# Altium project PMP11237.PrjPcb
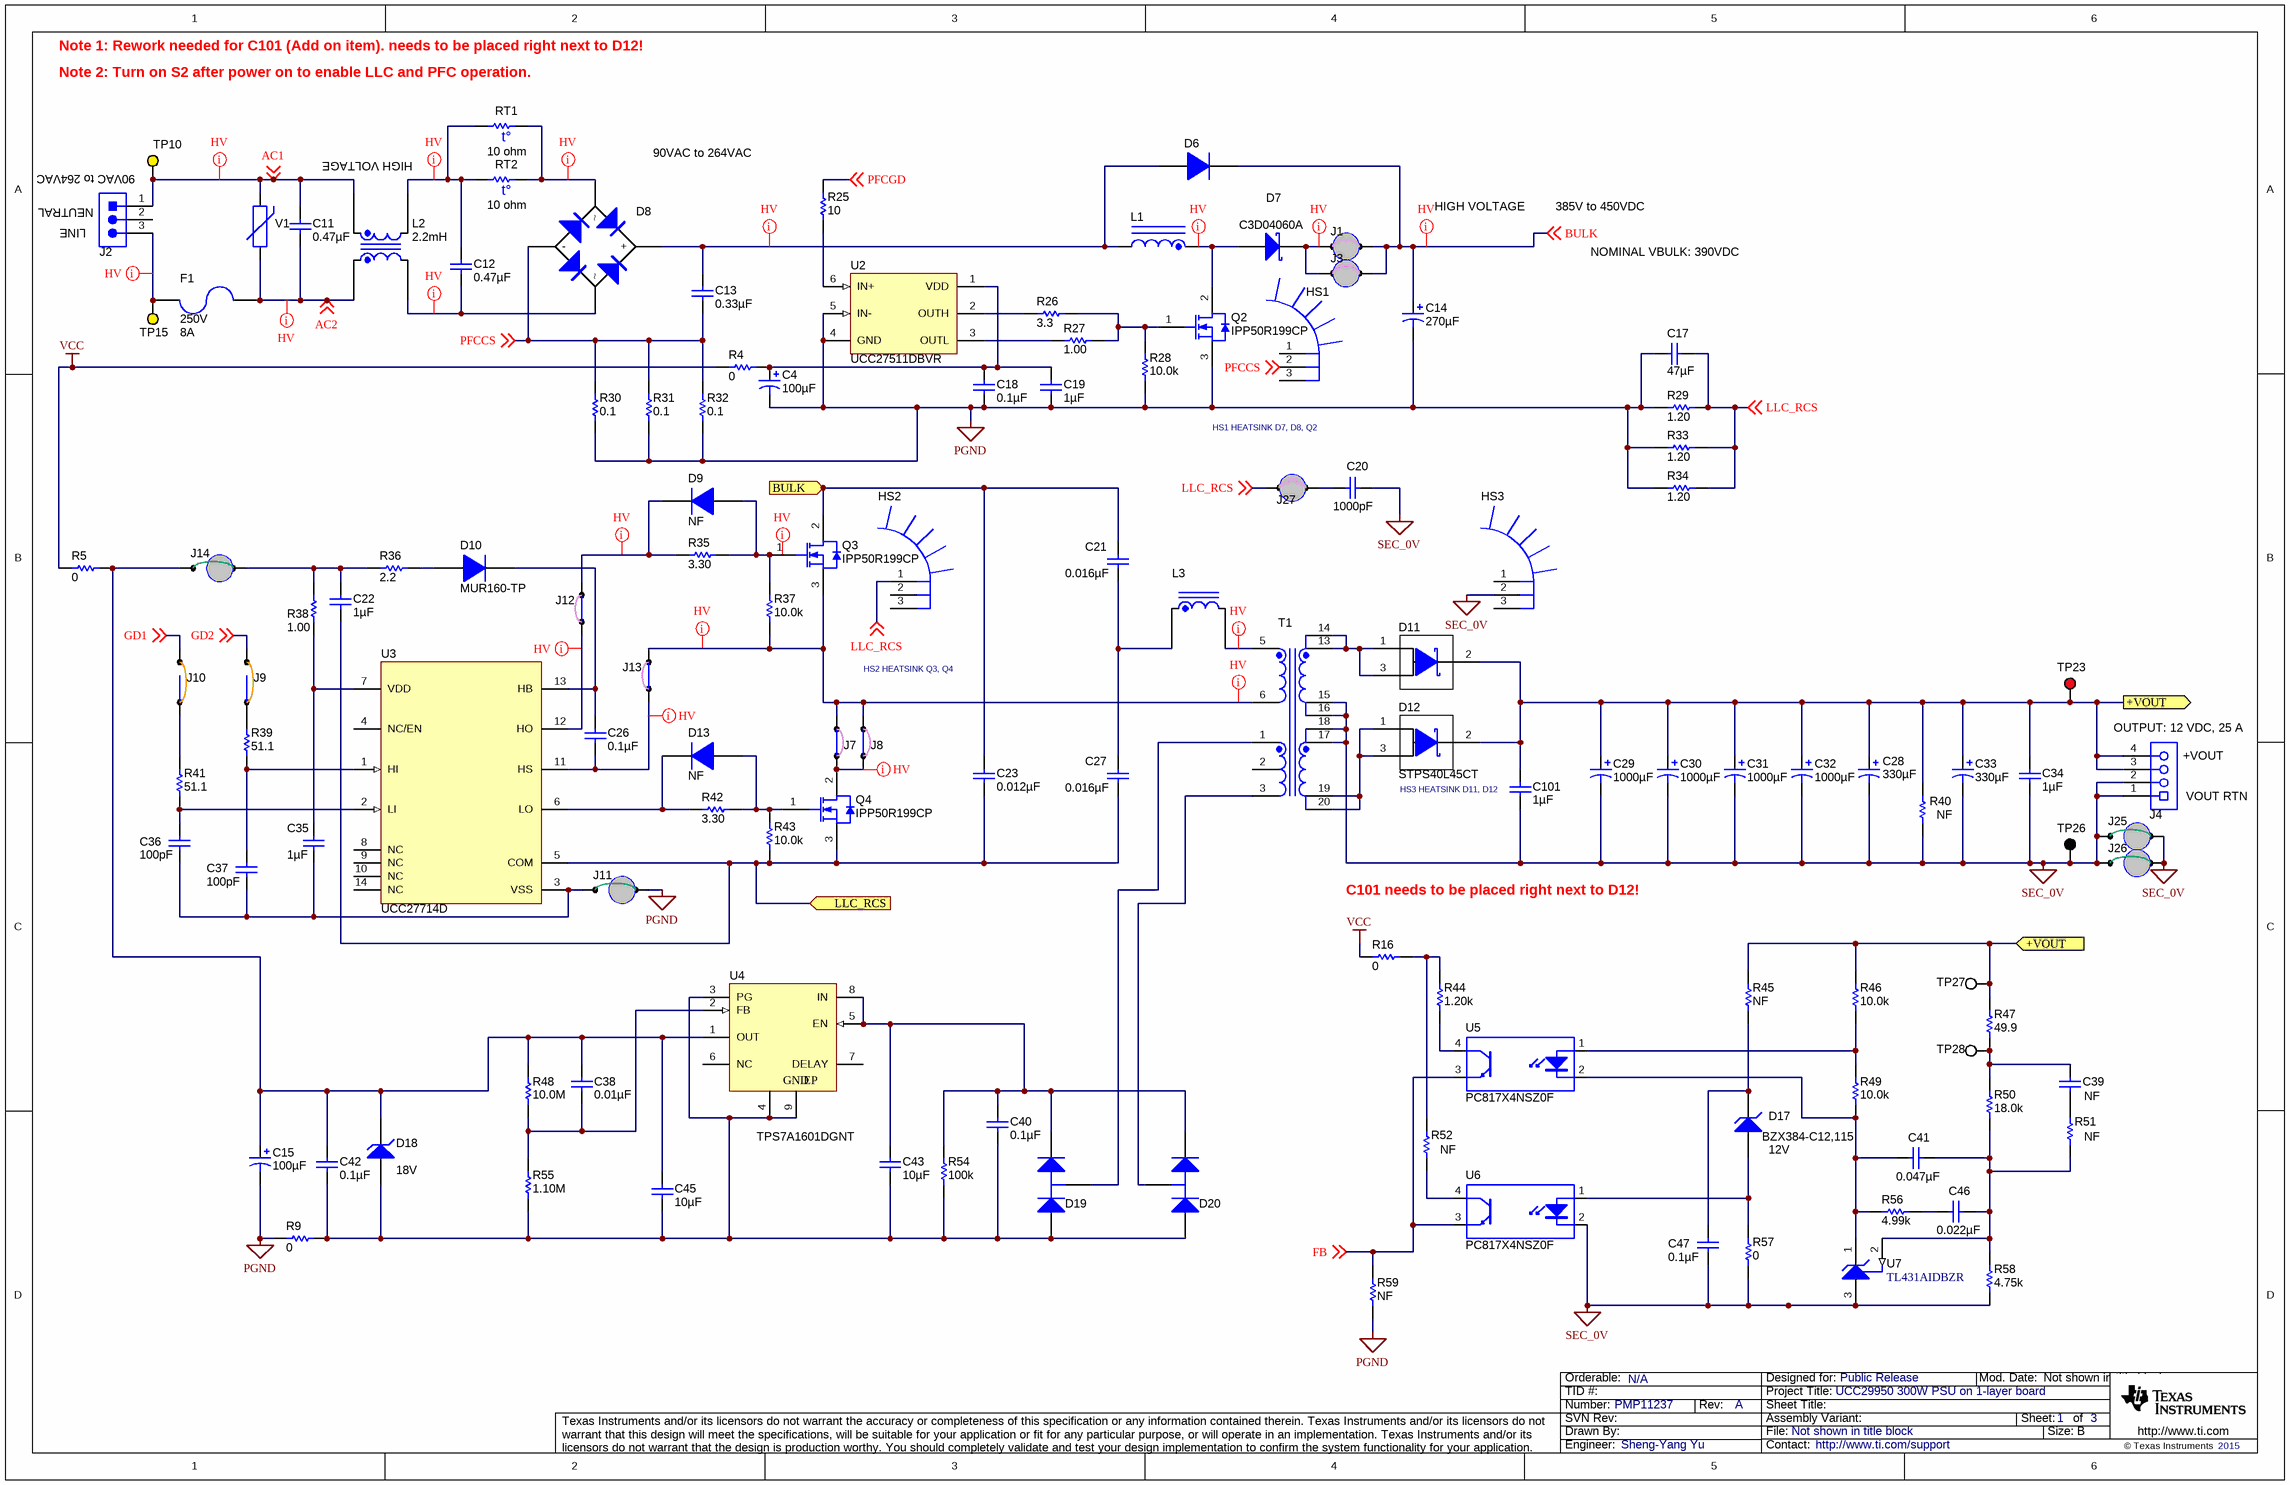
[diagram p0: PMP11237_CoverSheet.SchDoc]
CopyrightYear: 2015; EVM_Orderable: N/A; PCB_Layout: Sheng-Yang Yu; PCB_Rev: A; PRJ_Customer: Public Release; PRJ_Engineer: Sheng-Yang Yu; PRJ_Number: PMP11237; PRJ_Title: UCC29950 300W PSU on 1-layer board; SCH_Rev: A; TechSupport: http://www.ti.com/support
3 sheets, 215 parts. Net scope: flat (ports and power ports of the same name join across sheets).
Board file: PMP11237_TID.PcbDoc
Sheets:
  PMP11237_CoverSheet.SchDoc
  PMP11237_BlankSheet.SchDoc
  PMP11237_TID_Hardware.SchDoc

## Sheet PMP11237_CoverSheet.SchDoc
size 431 x 279 mm; Date: Not shown in title block; ApprovedBy: Not shown in title block; CheckedBy: Not shown in title block; Author: Not shown in title block; CompanyName: Not shown in title block; Engineer: Not shown in title block; Organization: Not shown in title block; Address1: Not shown in title block; Address2: Not shown in title block; Address3: Not shown in title block; Address4: Not shown in title block; DocumentNumber: 1; Revision: Use project parameter SCH_Rev; SheetNumber: 1; SheetTotal: 3; PageSetup: Record=PageOptions¦CenterHorizontal=True¦CenterVertical=True¦PrintScale=1.00¦XCorrection=1.00¦YCorrection=1.00¦PrintKind=0¦BorderSize=5000000¦LeftOffset=0¦BottomOffset=0¦Orientation=2¦PaperLength=1000¦PaperWidth=1000¦Scale=100¦PaperSource=15¦PrintQuality=600¦MediaType=1¦DitherType=10¦PaperKind=Letter¦PrintScaleMode=1

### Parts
C4  ValueDisplayed: 100µF  [CAPPR250W50D630H1120]  (hidden comment: EEU-EB1E101S)
C11  ValueDisplayed: 0.47µF  [CAPRR2250W80L2550T850H1750]  (hidden comment: ECQ-U2A474ML)
C12  ValueDisplayed: 0.47µF  [CAPRR2250W80L2550T850H1750]  (hidden comment: ECQ-U2A474ML)
C13  ValueDisplayed: 0.33µF  [CAPRR1500W80L1750T950H1750]  (hidden comment: ECQ-U2A334ML)
C14  ValueDisplayed: 270µF  [380LQ_3000x3000]  (hidden comment: 380LQ271M450K022)
C15  ValueDisplayed: 100µF  [CAPPR250W50D630H1120]  (hidden comment: EEU-EB1E101S)
C17  ValueDisplayed: 47µF  [1210]  (hidden comment: GRM32ER70J476KE20L)
C18  ValueDisplayed: 0.1µF  [0805_HV]  (hidden comment: 08055C104JAT2A)
C19  ValueDisplayed: 1µF  [0805_HV]  (hidden comment: GRM21BR71H105KA12L)
C20  ValueDisplayed: 1000pF  [DE_800x1200x800]  (hidden comment: DE1E3KX102MA5BA01)
C21  value 0.016µF  [ECWH_8123HA]  (hidden comment: ECW-F6163JL)
C22  ValueDisplayed: 1µF  [0603]  (hidden comment: UMK107AB7105KA-T)
C23  ValueDisplayed: 0.012µF  [ECWH_8123HA]  (hidden comment: ECW-H8123HA)
C26  ValueDisplayed: 0.1µF  [1206]  (hidden comment: C3216C0G1E104J)
C27  value 0.016µF  [ECWH_8123HA]  (hidden comment: ECW-F6163JL)
C28  ValueDisplayed: 330µF  [PS_1000x1250]  (hidden comment: APS-160ELL331MJC5S)
C29  ValueDisplayed: 1000µF  [FR_800x2000]  (hidden comment: EEU-FR1C102L)
C30  ValueDisplayed: 1000µF  [FR_800x2000]  (hidden comment: EEU-FR1C102L)
C31  ValueDisplayed: 1000µF  [FR_800x2000]  (hidden comment: EEU-FR1C102L)
C32  ValueDisplayed: 1000µF  [FR_800x2000]  (hidden comment: EEU-FR1C102L)
C33  ValueDisplayed: 330µF  [PS_1000x1250]  (hidden comment: APS-160ELL331MJC5S)
C34  ValueDisplayed: 1µF  [0805_HV]  (hidden comment: GRM21BR71H105KA12L)
C35  ValueDisplayed: 1µF  [1206]  (hidden comment: 12063C105KAT2A)
C36  ValueDisplayed: 100pF  [0603]  (hidden comment: 06035A101FAT2A)
C37  ValueDisplayed: 100pF  [0603]  (hidden comment: 06035A101FAT2A)
C38  ValueDisplayed: 0.01µF  [0603]  (hidden comment: C0603C103K5RACTU)
C39  NF  [0603]
C40  ValueDisplayed: 0.1µF  [0805_HV]  (hidden comment: 08055C104JAT2A)
C41  ValueDisplayed: 0.047µF  [0805_HV]  (hidden comment: 08055C473KAT2A)
C42  ValueDisplayed: 0.1µF  [0805_HV]  (hidden comment: 08055C104JAT2A)
C43  ValueDisplayed: 10µF  [1206_190]  (hidden comment: CGA5L3X5R1H106K160AB)
C45  ValueDisplayed: 10µF  [1206_190]  (hidden comment: CGA5L3X5R1H106K160AB)
C46  ValueDisplayed: 0.022µF  [0603]  (hidden comment: 885012206091)
C47  ValueDisplayed: 0.1µF  [0603]  (hidden comment: C0603C104K4RACTU)
C101  ValueDisplayed: 1µF  [1206]  (hidden comment: CC1206KKX7R7BB105)
D6  1N5406  [DO-201AD]  (value not drawn)
D7  C3D04060A  [TO-220-F2]
D8  GBU8J-BP  [GBU]  (value not drawn)
D9  NF  [sod-323]
D10  MUR160-TP  [DO-41]
D11  STPS40L45CT  [TO-220AB]  (value not drawn)
D12  STPS40L45CT  [TO-220AB]
D13  NF  [sod-323]
D17  BZX384-C12,115  value 12V  [sod-323]
D18  value 18V  [SOD-123]  (hidden comment: MMSZ5248B-7-F)
D19  BAV99,215  [SOT-23]  (value not drawn)
D20  BAV99,215  [SOT-23]  (value not drawn)
F1  VAC_V: 250V  Irating_A: 8A  [FUSE_0216]  (hidden comment: 0216008.MXESPP)
HS1  782653B04250G  [HEATSINK_782653B04250G]  (value not drawn)
HS2  782653B04250G  [HEATSINK_782653B04250G]  (value not drawn)
HS3  782653B04250G  [HEATSINK_782653B04250G]  (value not drawn)
J1  923345-07-C  [CONN_923345-07-C]  (value not drawn)
J2  1-1318301-3  [TE_1-1318301-3]  (value not drawn)
J3  923345-07-C  [CONN_923345-07-C]  (value not drawn)
J4  ED120/4DS  [CONN_ED120_4DS]  (value not drawn)
J7  923345-07-C  [CONN_923345-07-C]  (value not drawn)
J8  923345-07-C  [CONN_923345-07-C]  (value not drawn)
J9  923345-03-C  [923345-03-C]  (value not drawn)
J10  923345-03-C  [923345-03-C]  (value not drawn)
J11  923345-05-C  [923345-05-C]  (value not drawn)
J12  923345-07-C  [CONN_923345-07-C]  (value not drawn)
J13  923345-07-C  [CONN_923345-07-C]  (value not drawn)
J14  923345-05-C  [923345-05-C]  (value not drawn)
J25  923345-05-C  [923345-05-C]  (value not drawn)
J26  923345-05-C  [923345-05-C]  (value not drawn)
J27  923345-07-C  [CONN_923345-07-C]  (value not drawn)
L1  RLTI-1108  [RLTI-1108]  (value not drawn)
L2  ValueDisplayed: 2.2mH  [WE-CMB_XL]  (hidden comment: 7448258022)
L3  75PR8106  [Vitec_75P8106]  (value not drawn)
Q2  IPP50R199CP  [TO-262_100mil]
Q3  IPP50R199CP  [TO-262_100mil]
Q4  IPP50R199CP  [TO-262_100mil]
R4  ValueDisplayed: 0  [1206]  (hidden comment: CRCW12060000Z0EA)
R5  ValueDisplayed: 0  [1206]  (hidden comment: CRCW12060000Z0EA)
R9  ValueDisplayed: 0  [1206]  (hidden comment: CRCW12060000Z0EA)
R16  ValueDisplayed: 0  [1206]  (hidden comment: CRCW12060000Z0EA)
R25  ValueDisplayed: 10  [0603]  (hidden comment: CRCW060310R0JNEA)
R26  ValueDisplayed: 3.3  [0603]  (hidden comment: CRCW06033R30JNEA)
R27  ValueDisplayed: 1.00  [0603]  (hidden comment: CRCW06031R00FKEA)
R28  value 10.0k  [0603]  (hidden comment: CRCW060310K0FKEA)
R29  ValueDisplayed: 1.20  [2512M]  (hidden comment: ERJ-1TRQF1R2U)
R30  ValueDisplayed: 0.1  [2512]  (hidden comment: CSRN2512FTR100)
R31  ValueDisplayed: 0.1  [2512]  (hidden comment: CSRN2512FTR100)
R32  ValueDisplayed: 0.1  [2512]  (hidden comment: CSRN2512FTR100)
R33  ValueDisplayed: 1.20  [2512M]  (hidden comment: ERJ-1TRQF1R2U)
R34  ValueDisplayed: 1.20  [2512M]  (hidden comment: ERJ-1TRQF1R2U)
R35  value 3.30  [1206]  (hidden comment: ERJ-8RQF3R3V)
R36  ValueDisplayed: 2.2  [0805_HV]  (hidden comment: CRCW08052R20JNEA)
R37  value 10.0k  [0603]  (hidden comment: CRCW060310K0FKEA)
R38  value 1.00  [0805_HV]  (hidden comment: ERJ-6RQF1R0V)
R39  ValueDisplayed: 51.1  [0603]  (hidden comment: CRCW060351R1FKEA)
R40  NF  [1206]
R41  ValueDisplayed: 51.1  [0603]  (hidden comment: CRCW060351R1FKEA)
R42  value 3.30  [1206]  (hidden comment: ERJ-8RQF3R3V)
R43  value 10.0k  [0603]  (hidden comment: CRCW060310K0FKEA)
R44  ValueDisplayed: 1.20k  [1206]  (hidden comment: RC1206FR-071K2L)
R45  ValueDisplayed: NF  [1206]  (hidden comment: CRCW1206100RFKEA)
R46  ValueDisplayed: 10.0k  [0805_HV]  (hidden comment: CRCW080510K0FKEA)
R47  value 49.9  [1206]  (hidden comment: ERJ-8ENF49R9V)
R48  ValueDisplayed: 10.0M  [0603]  (hidden comment: RC0603FR-0710ML)
R49  value 10.0k  [0603]  (hidden comment: CRCW060310K0FKEA)
R50  value 18.0k  [0603]  (hidden comment: RC0603FR-0718KL)
R51  NF  [0603]
R52  NF  [0603]
R54  ValueDisplayed: 100k  [0603]  (hidden comment: CRCW0603100KFKEA)
R55  ValueDisplayed: 1.10M  [0603]  (hidden comment: CRCW06031M10FKEA)
R56  ValueDisplayed: 4.99k  [0603]  (hidden comment: CPF0603B4K99E)
R57  value 0  [0603]  (hidden comment: CRCW06030000Z0EA)
R58  ValueDisplayed: 4.75k  [0603]  (hidden comment: CRCW06034K75FKEA)
R59  ValueDisplayed: NF  [1206]  (hidden comment: CRCW12061K00FKEA)
RT1  value 10 ohm  [Thermistor_CL-40]  (hidden comment: CL-60)
RT2  value 10 ohm  [Thermistor_CL-40]  (hidden comment: CL-60)
T1  RLTI-1115  [Renco_RLTI-1115]  (value not drawn)
TP10  5014  [Keystone5014]  (value not drawn)
TP15  5014  [Keystone5014]  (value not drawn)
TP23  5010  [Keystone5010]  (value not drawn)
TP26  5011  [Keystone5011]  (value not drawn)
TP27  5012  [Keystone5012]  (value not drawn)
TP28  5012  [Keystone5012]  (value not drawn)
U2  UCC27511DBVR  [DBV0006A_N]
U3  UCC27714D  [D0014A_N]
U4  TPS7A1601DGNT  [DGN0008C_N]
U5  PC817X4NSZ0F  [DIP762W60P254L460H350Q4B]
U6  PC817X4NSZ0F  [DIP762W60P254L460H350Q4B]
U7  TL431AIDBZR  [DBZ0003A_N]
V1  B72207S2301K101  [VAR_S07K300E2]  (value not drawn)

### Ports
+VOUT, BULK, LLC_RCS

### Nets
PGND: C4.2(-) C14.2(-) C15.2(-) C17.2 C18.2 C19.2 J11.2 Q2.3(S) R9.2 R28.2 R29.2 R30.1 R31.1 R32.1 R33.2 R34.2 R59.1 U2.4(GND) U2.5(IN-)
SEC_0V: C20.1 C28.2(-) C29.2(-) C30.2(-) C31.2(-) C32.2(-) C33.2(-) C34.2 C47.2 C101.2 HS3.2 J4.1 J4.2 J25.1 J25.2 J26.1 J26.2 R40.1 R57.1 R58.1 T1.15 T1.16 T1.17 T1.18 TP26.1 U6.2(K) U7.3(ANODE)
VCC: R4.1 R5.2 R16.1
+VOUT: C28.1(+) C29.1(+) C30.1(+) C31.1(+) C32.1(+) C33.1(+) C34.1 C101.1 D11.2(K) D12.2(K) J4.3 J4.4 R40.2 R45.2 R46.2 R47.2 TP23.1 TP27.1 ; port +VOUT
AC1: C11.1 J2.1 L2.1 TP10.1 V1.2 ; off-sheet AC1
AC2: C11.2 F1.1 L2.6 V1.1 ; off-sheet AC2
BULK: C14.1(+) D6.1(K) J1.2 J3.2 ; off-sheet BULK
BULK: C21.1 C23.1 Q3.2(D) ; port BULK  [a separate net that carries the same name]
FB: R59.2 U5.3(E) U6.3(E) ; off-sheet FB
GD1: J10.1 ; off-sheet GD1
GD2: J9.1 ; off-sheet GD2
LLC_RCS: C22.1 C23.2 C27.2 Q4.3(S) R43.2 U3.5(COM) ; port LLC_RCS
LLC_RCS: C17.1 HS2.1 J27.2 R29.1 R33.1 R34.1 ; off-sheet LLC_RCS  [a separate net that carries the same name]
PFCCS: C13.2 D8.4(-) HS1.2 R30.2 R31.2 R32.2 ; off-sheet PFCCS
PFCGD: R25.2 ; off-sheet PFCGD
NetC4_1: C4.1(+) C18.1 C19.1 R4.2 U2.1(VDD)
NetC12_1: C12.1 L2.12 RT1.1 RT2.1
NetC12_2: C12.2 D8.3 L2.7
NetC13_1: C13.1 D6.2(A) D8.1(+) L1.9
NetC15_1: C15.1(+) C38.1 C42.1 C45.1 D18.1(K) J14.1 R5.1 R48.2 U4.1(OUT)
NetC20_2: C20.2 J27.1
NetC21_2: C21.2 C27.1 L3.1
NetC22_2: C22.2 J14.2 R36.1 R38.2
NetC26_1: C26.1 D10.1(K) U3.13(HB)
NetC26_2: C26.2 J13.2 U3.11(HS)
NetC35_1: C35.1 R38.1 U3.7(VDD)
NetC35_2: C35.2 C36.2 C37.1 J11.1 U3.3(VSS)
NetC36_1: C36.1 R41.1 U3.2(LI)
NetC37_2: C37.2 R39.1 U3.1(HI)
NetC38_2: C38.2 R48.1 R55.1 U4.2(FB)
NetC39_1: C39.1 R47.1 R50.2 TP28.1
NetC39_2: C39.2 R51.1
NetC40_1: C40.1 C43.1 D19.2(K) D20.2(K) R54.2 U4.5(EN) U4.8(IN)
NetC40_2: C40.2 C42.2 C43.2 C45.2 D18.2(A) D19.1(A) D20.1(A) R9.1 R54.1 R55.2 U4.3(PG) U4.4(GND) U4.9(EP)
NetC41_1: C41.1 C46.1 R50.1 R51.2 R58.2 U7.2(REF)
NetC41_2: C41.2 R49.1 R56.1 U5.2(K) U7.1(CATHODE)
NetC46_2: C46.2 R56.2
NetC47_1: C47.1 D17.1(K) R45.1
NetD7_1: D7.1(K) J1.1 J3.1
NetD7_2: D7.2(A) L1.5 Q2.2(D)
NetD8_2: D8.2 RT1.2 RT2.2
NetD9_1: D9.1(K) J12.1 R35.1
NetD9_2: D9.2(A) Q3.1(G) R35.2 R37.2
NetD10_2: D10.2(A) R36.2
NetD11_1: D11.1(A) D11.3(A) T1.13 T1.14
NetD12_1: D12.1(A) D12.3(A) T1.19 T1.20
NetD13_1: D13.1(K) R42.1 U3.6(LO)
NetD13_2: D13.2(A) Q4.1(G) R42.2 R43.1
NetD17_2: D17.2(A) R57.2 U6.1(A)
NetD19_3: D19.3(C) T1.1
NetD20_3: D20.3(C) T1.3
NetF1_2: F1.2 J2.3 TP15.1
NetJ7_1: J7.1 J8.1 J13.1 Q3.3(S) R37.1 T1.6
NetJ7_2: J7.2 J8.2 Q4.2(D)
NetJ9_2: J9.2 R39.2
NetJ10_2: J10.2 R41.2
NetJ12_2: J12.2 U3.12(HO)
NetL3_6: L3.6 T1.5
NetQ2_1: Q2.1(G) R26.2 R27.2 R28.1
NetR16_2: R16.2 R44.2 R52.1
NetR25_1: R25.1 U2.6(IN+)
NetR26_1: R26.1 U2.2(OUTH)
NetR27_1: R27.1 U2.3(OUTL)
NetR44_1: R44.1 U5.4(C)
NetR46_1: R46.1 R49.2 U5.1(A)
NetR52_2: R52.2 U6.4(C)

Not connected (* = marked no-connect by the designer): HS1 1 3; HS2 2 3; HS3 1 3; J2 2; T1 2; U3 4(NC/EN) 8(NC) 9(NC) 10(NC) 14(NC); U4 6(NC) 7(DELAY)

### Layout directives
net class HV: (no net found under the mark), AC1, AC2, BULK, NetC12_1, NetC12_2, NetC13_1, NetC26_2, NetD7_1, NetD7_2, NetD8_2, NetD9_1, NetF1_2, NetJ7_1, NetJ7_2, NetJ12_2, NetL3_6

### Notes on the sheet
- Note 1: Rework needed for C101 (Add on item). needs to be placed right next to D12!
- (near RT1) Note 2: Turn on S2 after power on to enable LLC and PFC operation.
- HIGH VOLTAGE
- (near D8) 90VAC to 264VAC
- (near J2) NEUTRAL
- (near J2) LINE
- 90VAC to 264VAC
- 385V to 450VDC
- NOMINAL VBULK: 390VDC
- HS1 HEATSINK D7, D8, Q2
- HS2 HEATSINK Q3, Q4
- (near J4) OUTPUT: 12 VDC, 25 A
- (near J4) +VOUT
- HS3 HEATSINK D11, D12
- VOUT RTN
- C101 needs to be placed right next to D12!

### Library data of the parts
C4 C15 = EEU-EB1E101S: CAP, AL, 100 µF, 25 V, +/- 20%, TH; Manufacturer: Panasonic; Polarized: Y; CompType: Capacitor; Value: 100uF; U/M: EA; Cap_F: 0.0001; Tolerance_%: 20; Value1: Unknown; VDC_V: 25; Value2: 25V; IRMS_A: 0.095; TaMin_C: -40; TaMax_C: 105; Cap_Case: Radial 6.3x11.2
C11 C12 = ECQ-U2A474ML: CAP, Film, 0.47uF, 275V, +/-20%, TH; Manufacturer: Panasonic; Polarized: N; CompType: Capacitor; U/M: EA; Cap_F: 0.00000047; Tolerance_%: 20; Value1: Unknown; VDC_V: 275; TaMin_C: -40; TaMax_C: 100; Cap_Case: Radial 25x8.5x18.5
C13 = ECQ-U2A334ML: CAP, Film, 0.33uF, 275V, +/-20%, TH; Manufacturer: Panasonic; Polarized: N; CompType: Capacitor; U/M: EA; Cap_F: 0.00000033; Tolerance_%: 20; Value1: Unknown; VDC_V: 275; TaMin_C: -40; TaMax_C: 100; Cap_Case: Radial,17.5x17.5x9.5mm
C14 = 380LQ271M450K022: CAP, AL, 270 µF, 450 V, +/- 20%, 0.737 ohm, TH; Manufacturer: Cornell Dubilier Electronics; Polarized: Y; CompType: Capacitor; Value: 270uF; U/M: EA; Cap_F: 0.00027; Tolerance_%: 20; VDC_V: 450; Value2: 450V; ESR_ohm: 0.737; IRMS_A: 1.78; TaMin_C: -25; TaMax_C: 85; Cap_Case: 30x30mm
C17 = GRM32ER70J476KE20L: CAP, CERM, 47uF, 6.3V, +/-10%, X7R, 1210; Manufacturer: MuRata; Polarized: N; CompType: Capacitor; U/M: EA; Cap_F: 0.000047; Tolerance_%: 10; Value1: Unknown; VDC_V: 6.3; TaMin_C: -55; TaMax_C: 125
C18 C40 C42 = 08055C104JAT2A: CAP, CERM, 0.1uF, 50V, +/-5%, X7R, 0805; Manufacturer: AVX; Polarized: N; CompType: Capacitor; U/M: EA; Cap_F: 0.0000001; Tolerance_%: 5; ESR_Ohm: 0.024; Value1: 0.024 ohm; VDC_V: 50; TaMin_C: -55; TaMax_C: 125; Cap_Case: 0805
C19 C34 = GRM21BR71H105KA12L: CAP, CERM, 1uF, 50V, +/-10%, X7R, 0805; Manufacturer: MuRata; Polarized: N; CompType: Capacitor; U/M: EA; Cap_F: 0.000001; Tolerance_%: 10; Value1: Unknown; VDC_V: 50; TaMin_C: -55; TaMax_C: 125; Cap_Case: 0805
C20 = DE1E3KX102MA5BA01: CAP, CERM, 1000pF, 250V, +/-20%, E, Disc, 8x12mm; Manufacturer: MuRata; Polarized: N; CompType: Capacitor; U/M: EA; Cap_F: 0.000000001; Tolerance_%: 20; Value1: Unknown; VDC_V: 250; TaMin_C: -25; TaMax_C: 85
C21 C27 = ECW-H8123HA: CAP FILM 0.016UF 630VDC RADIAL; Manufacturer: Panasonic Electronic Components; Dielectric Material: Polypropylene (PP), Metallized; Voltage Rating - DC: 630V; Tolerance_%: ±5%
C22 = UMK107AB7105KA-T: CAP, CERM, 1 µF, 50 V, +/- 10%, X7R, 0603; Manufacturer: Taiyo Yuden; Polarized: N; CompType: Capacitor; Value: 1uF; U/M: EA; Cap_F: 0.000001; Tolerance_%: 10; Value1: Unknown; VDC_V: 50; Value2: 50V; TaMin_C: -55; TaMax_C: 125
C23 = ECW-H8123HA: CAP, Film, 0.012uF, 800V, +/-3%, TH; Manufacturer: Panasonic; Polarized: N; CompType: Capacitor; U/M: EA; Cap_F: 0.000000012; Tolerance_%: 3; Value1: Unknown; VDC_V: 800; TaMin_C: -40; TaMax_C: 105
C26 = C3216C0G1E104J: CAP, CERM, 0.1 µF, 25 V, +/- 5%, C0G/NP0, 1206; Manufacturer: TDK; Polarized: N; CompType: Capacitor; Value: 0.1uF; U/M: EA; Cap_F: 0.0000001; Tolerance_%: 5; Value1: Unknown; VDC_V: 25; Value2: 25V; TaMin_C: -55; TaMax_C: 125
C28 C33 = APS-160ELL331MJC5S: CAP, AL, 330uF, 16V, +/-20%, 0.014 ohm, TH; Manufacturer: Nippon Chemi-Con; Polarized: Y; CompType: Capacitor; U/M: EA; Cap_F: 0.00033; Tolerance_%: 20; VDC_V: 16; ESR_Ohm: 0.014; IRMS_A: 5.05; TaMin_C: -55; TaMax_C: 105
C29-C32 = EEU-FR1C102L: CAP, AL, 1000uF, 16V, +/-20%, 0.03 ohm, TH; Manufacturer: Panasonic; Polarized: Y; CompType: Capacitor; U/M: EA; Cap_F: 0.001; Tolerance_%: 20; VDC_V: 16; ESR_Ohm: 0.03; IRMS_A: 1.56; TaMin_C: -40; TaMax_C: 105; Cap_Case: 8x20
C35 = 12063C105KAT2A: CAP, CERM, 1 µF, 25 V, +/- 10%, X7R, 1206; Manufacturer: AVX; Polarized: N; CompType: Capacitor; Value: 1uF; U/M: EA; Cap_F: 0.000001; Tolerance_%: 10; ESR_ohm: 0.013; Value1: 0.013 ohm; VDC_V: 25; Value2: 25V; TaMin_C: -55; TaMax_C: 125
C36 C37 = 06035A101FAT2A: CAP, CERM, 100pF, 50V, +/-1%, C0G/NP0, 0603; Manufacturer: AVX; CompType: Capacitor; Tolerance_%: 1; Value1: Unknown; VDC_V: 50; U/M: EA; Polarized: N; Cap_F: 0.0000000001; TaMin_C: -55; TaMax_C: 125
C38 = C0603C103K5RACTU: CAP, CERM, 0.01 µF, 50 V, +/- 10%, X7R, 0603; Manufacturer: Kemet; Polarized: N; CompType: Capacitor; Value: 0.01uF; U/M: EA; Cap_F: 0.00000001; Tolerance_%: 10; Value1: Unknown; VDC_V: 50; Value2: 50V; TaMin_C: -55; TaMax_C: 125
C39 = GRM1885C1E102JA01D: CAP, CERM, 1000pF, 25V, +/-5%, C0G/NP0, 0603; Manufacturer: MuRata; Polarized: N; CompType: Capacitor; U/M: EA; Cap_F: 0.000000001; Tolerance_%: 5; Value1: Unknown; VDC_V: 25; TaMin_C: -55; TaMax_C: 125
C41 = 08055C473KAT2A: CAP, CERM, 0.047uF, 50V, +/-10%, X7R, 0805; Manufacturer: AVX; Polarized: N; CompType: Capacitor; U/M: EA; Cap_F: 0.000000047; Tolerance_%: 10; ESR_Ohm: 0.035; Value1: 0.035 ohm; VDC_V: 50; TaMin_C: -55; TaMax_C: 125; Cap_Case: 0805
C43 C45 = CGA5L3X5R1H106K160AB: CAP, CERM, 10 µF, 50 V, +/- 10%, X5R, 1206_190; Manufacturer: TDK; Polarized: N; CompType: Capacitor; Value: 10uF; U/M: EA; Cap_F: 0.00001; Tolerance_%: 10; Value1: Unknown; VDC_V: 50; Value2: 50V; TaMin_C: -55; TaMax_C: 85
C46 = 885012206091: CAP, CERM, 0.022 µF, 50 V, +/- 10%, X7R, 0603; Manufacturer: Wurth Elektronik; Polarized: N; CompType: Capacitor; Value: 0.022uF; U/M: EA; Cap_F: 0.000000022; Tolerance_%: 10; Value1: Unknown; VDC_V: 50; Value2: 50V; TaMin_C: -55; TaMax_C: 125; AEC Category: Q200
C47 = C0603C104K4RACTU: CAP, CERM, 0.1uF, 16V, +/-10%, X7R, 0603; Manufacturer: Kemet; Polarized: N; CompType: Capacitor; U/M: EA; Cap_F: 0.0000001; Tolerance_%: 10; Value1: Unknown; VDC_V: 16; TaMin_C: -55; TaMax_C: 125
C101 = CC1206KKX7R7BB105: CAP, CERM, 1 µF, 16 V, +/- 10%, X7R, 1206; Manufacturer: Yageo America; Polarized: N; CompType: Capacitor; Value: 1uF; U/M: EA; Cap_F: 0.000001; Tolerance_%: 10; Value1: Unknown; VDC_V: 16; Value2: 16V; TaMin_C: -55; TaMax_C: 125; AEC Category: Q200
D6 = 1N5406: Diode, Switching-Bridge, 600V, 3A, TH; Manufacturer: Vishay-Semiconductor; U/M: EA; Vf_V: 1.2; Value2: 1.2V; Io_A: 3; Vr_V: 600; TJmax_C: 150
D7 = C3D04060A: Diode, Schottky, 600V, 4A, TH; Manufacturer: Cree; U/M: EA; Vf_V: 1.8; Value2: 1.8V; Io_A: 4; Vr_V: 600; TJmax_C: 175; RJC_CperW: 11.5
D8 = GBU8J-BP: Diode, Switching-Bridge, 420V, 8A, TH; Manufacturer: Micro Commercial Components; U/M: EA; Vf_V: 1; Value2: 1V; Io_A: 8; Vr_V: 420; TJmax_C: 175
D9 D13 = BAS316,115: Diode, Ultrafast, 100V, 0.25A, SOD-323; Manufacturer: NXP Semiconductor; U/M: EA; Vf_V: 1.4; Value2: 1.4V; Io_A: 0.25; Vr_V: 100; TJmax_C: 150
D10 = 1N4005-T: DIODE GEN PURP 600V 1A DO41; Manufacturer: Micro Commercial Co; U/M: EA; Vf_V: 1; Value2: 1V; Vr_V: 600; TJmax_C: 150; Type: Standard Recovery Rectifier
D11 D12 = STPS40L45CT: Diode, Schottky, 45V, 20A, TH; Manufacturer: ST Microelectronics; U/M: EA; Vf_V: 0.49; Value2: 0.49V; Io_A: 20; Vr_V: 45; TJmax_C: 150; RJC_CperW: 0.8
D17 = BZX384-C12,115: Diode, Zener, 12V, 300mW, SOD-323; Manufacturer: NXP Semiconductor; SymbolCreator: a0412235; U/M: EA; Power_W: 0.3; Vz_V: 12; Value1: 0.3W; RJA_CperW: 415
D18 = MMSZ5248B-7-F: Diode, Zener, 18V, 500mW, SOD-123; Manufacturer: Diodes Inc.; SymbolCreator: a0412235; U/M: EA; Power_W: 0.5; Vz_V: 18; Value1: 0.5W; RJA_CperW: 350
D19 D20 = BAV99,215: Diode, Switching, 100V, 0.215A, SOT-23; Manufacturer: NXP Semiconductor; U/M: EA; Vf_V: 1.25; Value2: 1.25V; Io_A: 0.215; Vr_V: 100; TJmax_C: 150
F1 = 0216008.MXESPP: Fuse, 8A, 250V, TH; Manufacturer: Littelfuse; U/M: EA; OpeningTime_200%_max: 30; VDC_V: 250; Rtyp_Ohm: 0.0123; Soldering_Wave_MaxTemp_C: 260; Soldering_Wave_MaxTime_s: 5
HS1-HS3 = 782653B04250G: HEATSINK VERT MAX CLIP, BLACK, 4.25 INCHES; Manufacturer: Aavid; SymbolCreator: a0411947
J1 J3 J7 J8 J12 J13 J27 = 923345-07-C: Jumper Wire, 700mil spacing, Violet, pkg of 150, TH; Manufacturer: 3M; SymbolCreator: a0412235; U/M: EA
J2 = 1-1318301-3: Header, 312mil, 3x1, Tin, TH; Manufacturer: TE Connectivity; SymbolCreator: a0799628; U/M: EA
J4 = ED120/4DS: Terminal Block, 4x1, 5.08mm, TH; Manufacturer: On-Shore Technology; SymbolCreator: a0411947; U/M: EA
J9 J10 = 923345-03-C: Jumper Wire, 300mil spacing, Orange, pkg of 200; Manufacturer: 3M; SymbolCreator: a0412235; U/M: EA
J11 J14 J25 J26 = 923345-05-C: Jumper Wire, 500mil spacing, Green, pkg of 200; Manufacturer: 3M; SymbolCreator: a0412235; U/M: EA
L1 = RLTI-1108: Inductor, ?, , A, TH; Manufacturer: Renco Electronics; SymbolCreator: a0411947; U/M: EA
L2 = 7448258022: Coupled inductor, 2.2mH, 8A, 0.014 ohm, +/-30%, TH; Manufacturer: Wurth Elektronik eiSos; SymbolCreator: a0799628; Ind_H: 2.2E-3; DCR_ohm: 0.014; Isat: 8; Tolerance_%: 30
L3 = 75PR8106: Inductor, Shielded, ?, 55uH, A, 0.065 ohm, TH; Manufacturer: Vitec Corporation; SymbolCreator: x0208326; Ind_H: 55.0E-6; ValueDisplayed: 55µH; DCR_ohm: 0.065; U/M: EA
Q2-Q4 = AOW25S65: MOSFET N-CH 550V 17A TO-220; Manufacturer: Infineon; Alternate Manufacturer: None; U/M: EA; ChType: N; Value: 650V; VdsMax_V: 650; Value1: ? ohm; QgTyp_nC: 26.4; IdsMax_A: 25
R4 R5 R9 R16 = CRCW12060000Z0EA: RES, 0, 5%, 0.25 W, 1206; Manufacturer: Vishay-Dale; CompType: Resistor; Value: 0; Value_Code: 0000; Tolerance_%: 5; Power_W: 0.25; Value2: 0.25W; VDC_V: 200; TempCo: 200 ppm/C; EIA_Code: E24; U/M: EA
R25 = CRCW060310R0JNEA: RES, 10, 5%, 0.1 W, 0603; Manufacturer: Vishay-Dale; CompType: Resistor; Value: 10; Value_Code: 10R0; Tolerance_%: 5; Power_W: 0.1; Value2: 0.1W; VDC_V: 75; TempCo: 200 ppm/C; EIA_Code: E24; U/M: EA
R26 = CRCW06033R30JNEA: RES, 3.3, 5%, 0.1 W, 0603; Manufacturer: Vishay-Dale; CompType: Resistor; Value: 3.3; Value_Code: 3R30; Tolerance_%: 5; Power_W: 0.1; Value2: 0.1W; VDC_V: 75; TempCo: 200 ppm/C; EIA_Code: E24; U/M: EA
R27 = CRCW06031R00FKEA: RES, 1.00, 1%, 0.1 W, 0603; Manufacturer: Vishay-Dale; CompType: Resistor; Value: 1.00; Res_ohm: 1; Value_Code: 1R00; Power_W: 0.1; Value2: 0.1W; VDC_V: 75; TempCo: 100 ppm/C; EIA_Code: E96; U/M: EA
R28 R37 R43 R49 = CRCW060310K0FKEA: RES, 10.0k ohm, 1%, 0.1W, 0603; Manufacturer: Vishay-Dale; CompType: Resistor; Res_ohm: 10000; Value_Code: 10k0; Tolerance_%: 1; Power_W: 0.1; VDC_V: 75; TempCo: 100 ppm/C; EIA_Code: E96; U/M: EA
R29 R33 R34 = ERJ-1TRQF1R2U: RES, 1.20, 1%, 1 W, 2512; Manufacturer: Panasonic; Power_W: 1; Value: 1.20; TempCo: 100 ppm/C; CompType: Resistor; Res_ohm: 1.2; Value_Code: 1R20; Value2: 1W; U/M: EA
R30 R31 = CSRN2512FTR100: RES, 0.1, 1%, 2 W, 2512; Manufacturer: Stackpole Electronics Inc; Value: 0.1; TempCo: 200 ppm/C; Tolerance_%: 1; Power_W: 2; CompType: Resistor; Value_Code: R100; Value2: 2W; VDC_V: 200; EIA_Code: E96; U/M: EA
R32 = CSRN2512FTR100: RES, 0.1, 1%, 2 W, 2512; Manufacturer: Stackpole Electronics Inc; TempCo: 200 ppm/C; Tolerance_%: 1; Power_W: 2; Value: 0.1; CompType: Resistor; Value_Code: R100; Value2: 2W; VDC_V: 200; EIA_Code: E96; U/M: EA
R35 R42 = ERJ-8RQF3R3V: RES, 3.30 ohm, 1%, 0.25W, 1206; Manufacturer: Panasonic; CompType: Resistor; Res_ohm: 3.3; Value_Code: 3R30; Tolerance_%: 1; Power_W: 0.25; TempCo: 200 ppm/C; U/M: EA
R36 = CRCW08052R20JNEA: RES, 2.2, 5%, 0.125 W, 0805; Manufacturer: Vishay-Dale; CompType: Resistor; Value: 2.2; Value_Code: 2R20; Tolerance_%: 5; Power_W: 0.125; Value2: 0.125W; VDC_V: 150; TempCo: 200 ppm/C; EIA_Code: E24; U/M: EA
R38 = ERJ-6RQF1R0V: RES, 1.00 ohm, 1%, 0.125W, 0805; Manufacturer: Panasonic; CompType: Resistor; Res_ohm: 1; Value_Code: 1R00; Power_W: 0.125; TempCo: 200 ppm/C; EIA_Code: E96; U/M: EA
R39 R41 = CRCW060351R1FKEA: RES, 51.1, 1%, 0.1 W, 0603; Manufacturer: Vishay-Dale; CompType: Resistor; Value: 51.1; Value_Code: 51R1; Tolerance_%: 1; Power_W: 0.1; Value2: 0.1W; VDC_V: 75; TempCo: 100 ppm/C; EIA_Code: E96; U/M: EA
R40 = CRCW12061K00FKEA: RES, 1.00k ohm, 1%, 0.25W, 1206; Manufacturer: Vishay-Dale; CompType: Resistor; Res_ohm: 1000; Value_Code: 1k00; Tolerance_%: 1; Power_W: 0.25; VDC_V: 200; TempCo: 100 ppm/C; EIA_Code: E96; U/M: EA
R44 = RC1206FR-071K2L: RES, 1.20 k, 1%, 0.25 W, 1206; Manufacturer: Yageo America; CompType: Resistor; Value: 1.20k; Res_ohm: 1200; Value_Code: 1k20; Tolerance_%: 1; Power_W: 0.25; Value2: 0.25W; VDC_V: 200; TempCo: 100 ppm/C; U/M: EA
R45 = CRCW1206100RFKEA: RES, 100, 1%, 0.25 W, 1206; Manufacturer: Vishay-Dale; CompType: Resistor; Value: 100; Value_Code: 100R; Tolerance_%: 1; Power_W: 0.25; Value2: 0.25W; VDC_V: 200; TempCo: 100 ppm/C; EIA_Code: E96; U/M: EA
R46 = CRCW080510K0FKEA: RES, 10.0 k, 1%, 0.125 W, 0805; Manufacturer: Vishay-Dale; CompType: Resistor; Value: 10.0k; Res_ohm: 10000; Value_Code: 10k0; Tolerance_%: 1; Power_W: 0.125; Value2: 0.125W; VDC_V: 150; TempCo: 100 ppm/C; EIA_Code: E96; U/M: EA; AEC Category: Q200
R47 = ERJ-8ENF49R9V: RES, 49.9 ohm, 1%, 0.25W, 1206; Manufacturer: Panasonic; CompType: Resistor; Value_Code: 49R9; Tolerance_%: 1; Power_W: 0.25; VDC_V: 200; TempCo: 100 ppm/C; EIA_Code: E96; U/M: EA
R48 = RC0603FR-0710ML: RES, 10.0 M, 1%, 0.1 W, 0603; Manufacturer: Yageo America; CompType: Resistor; Value: 10.0Meg; Res_ohm: 10000000; Value_Code: 10M0; Tolerance_%: 1; Power_W: 0.1; Value2: 0.1W; VDC_V: 150; TempCo: 200 ppm/C; EIA_Code: E96; U/M: EA
R50 = RC0603FR-0718KL: RES, 18.0k ohm, 1%, 0.1W, 0603; Manufacturer: Yageo America; CompType: Resistor; Res_ohm: 18000; Value_Code: 18k0; Tolerance_%: 1; Power_W: 0.1; VDC_V: 150; TempCo: 200 ppm/C; U/M: EA
R51 = CRCW060339K2FKEA: RES, 39.2k ohm, 1%, 0.1W, 0603; Manufacturer: Vishay-Dale; CompType: Resistor; Res_ohm: 39200; Value_Code: 39k2; Tolerance_%: 1; Power_W: 0.1; VDC_V: 75; TempCo: 100 ppm/C; EIA_Code: E96; U/M: EA
R52 = RC0603FR-071K2L: RES, 1.20k ohm, 1%, 0.1W, 0603; Manufacturer: Yageo America; CompType: Resistor; Res_ohm: 1200; Value_Code: 1k20; Tolerance_%: 1; Power_W: 0.1; VDC_V: 150; TempCo: 200 ppm/C; U/M: EA
R54 = CRCW0603100KFKEA: RES, 100 k, 1%, 0.1 W, 0603; Manufacturer: Vishay-Dale; CompType: Resistor; Value: 100k; Res_ohm: 100000; Tolerance_%: 1; Power_W: 0.1; Value2: 0.1W; VDC_V: 75; TempCo: 100 ppm/C; EIA_Code: E96; U/M: EA
R55 = CRCW06031M10FKEA: RES, 1.10 M, 1%, 0.1 W, 0603; Manufacturer: Vishay-Dale; CompType: Resistor; Value: 1.10Meg; Res_ohm: 1100000; Value_Code: 1M10; Tolerance_%: 1; Power_W: 0.1; Value2: 0.1W; VDC_V: 75; TempCo: 100 ppm/C; EIA_Code: E96; U/M: EA
R56 = CPF0603B4K99E: RES, 4.99 k, 0.1%, 0.063 W, 0603; Manufacturer: TE Connectivity; CompType: Resistor; Value: 4.99k; Res_ohm: 4990; Value_Code: 4k99; Tolerance_%: 0.1; Power_W: 0.063; Value2: 0.063W; VDC_V: 50; TempCo: 25 ppm/C; EIA_Code: E192; U/M: EA; AEC Category: Q200
R57 = CRCW06030000Z0EA: RES, 0 ohm, 5%, 0.1W, 0603; Manufacturer: Vishay-Dale; CompType: Resistor; Value_Code: 0000; Tolerance_%: 5; Power_W: 0.1; VDC_V: 75; TempCo: 200 ppm/C; EIA_Code: E24; U/M: EA
R58 = CRCW06034K75FKEA: RES, 4.75 k, 1%, 0.1 W, 0603; Manufacturer: Vishay-Dale; CompType: Resistor; Value: 4.75k; Res_ohm: 4750; Value_Code: 4k75; Tolerance_%: 1; Power_W: 0.1; Value2: 0.1W; VDC_V: 75; TempCo: 100 ppm/C; EIA_Code: E96; U/M: EA
R59 = CRCW12061K00FKEA: RES, 1.00 k, 1%, 0.25 W, 1206; Manufacturer: Vishay-Dale; CompType: Resistor; Value: 1.00k; Res_ohm: 1000; Value_Code: 1k00; Tolerance_%: 1; Power_W: 0.25; Value2: 0.25W; VDC_V: 200; TempCo: 100 ppm/C; EIA_Code: E96; U/M: EA
RT1 RT2 = CL-40: Thermistor NTC, 10 ohm, 25%, Disc, 220x770 mil; Manufacturer: GE Sensing; Tolerance_%: 25; Power_W: 180; TaMin_C: -50; TaMax_C: 175; U/M: EA
T1 = RLTI-1115: LLC Transformer, 280uH, TH; Manufacturer: Renco Electronics; SymbolCreator: x0208325; DCR_Ohm: 0.7; U/M: EA
TP10 TP15 = 5014: Test Point, Multipurpose, Yellow, TH; Manufacturer: Keystone; CompType: Test Point Loop; U/M: EA
TP23 = 5010: Test Point, Multipurpose, Red, TH; Manufacturer: Keystone; CompType: Test Point Loop; U/M: EA
TP26 = 5011: Test Point, Multipurpose, Black, TH; Manufacturer: Keystone; CompType: Test Point Loop; U/M: EA
TP27 TP28 = 5012: Test Point, Multipurpose, White, TH; Manufacturer: Keystone; CompType: Test Point Loop; U/M: EA
U2 = UCC27511DBVR: Single-Channel High-Speed Low-Side Gate Driver (with 4-A Peak Source and 8-A Peak Sink), DBV0006A; Alternate PartNumber: UCC27511DBVT; Manufacturer: Texas Instruments; SymbolCreator: a0411947; CompType: IC; U/M: EA
U3 = UCC27714D: High-Speed,4A, 600V High-side Low-side Gate Driver Device, D0014A; Manufacturer: Texas Instruments; SymbolCreator: a0411947; CompType: IC; U/M: EA
U4 = TPS7A1601DGNT: Single Output LDO, 100 mA, Adjustable 1.2 to 18.5 V Output, 3 to 60 V Input, with Enable and Power Good, 8-pin MSOP (DGN), -40 to 125 degC, Green (RoHS & no Sb/Br); Manufacturer: Texas Instruments; Alternate Manufacturer: None; Alternate PartNumber: Equivalent; Accuracy(%): 2; Iout(Max)(A): 0.1; Iq(Typ)(mA): 0.004; Power Good: TRUE; Rating: Catalog; SubFamily: Single Channel LDO; Vdo(Typ)(mV): 60; Vin(Min)(V): 3; Vout Adj(Max)(V): 18.5; Vout Adj(Min)(V): 1.2
U5 U6 = LTV-817: Opto-Isolator, 1 Channel, TH; CompType: OPTOCOUPLER; U/M: EA
U7 = TL431AIDBZR: Adjustable Precision Shunt Regulator, 34 ppm / degC, 100 mA, -40 to 85 degC, 3-pin SOT-23 (DBZ), Green (RoHS & no Sb/Br); Alternate Manufacturer: None; Alternate PartNumber: Equivalent; Manufacturer: Texas Instruments; Initial Accuracy @ 25/deg C(%): 1; Iout/Iz(Max)(mA): 100; Min Iz for Regulation(uA): 600; Rating: Catalog; SubFamily: Shunt Voltage Reference; Temp Coeff(Max)(ppm/ degree C): 92; Temp Coeff(Typ)(ppm/ degree C): 34; VO Adj(Max)(V): 36; VO Adj(Min)(V): 2.495
V1 = B72207S2301K101: Varistor, 300V, 1.75kA, 7MM Radial, TH; Manufacturer: EPCOS Inc; SymbolCreator: a0412235

## Sheet PMP11237_BlankSheet.SchDoc
size 431 x 279 mm; Date: Not shown in title block; ApprovedBy: Not shown in title block; CheckedBy: Not shown in title block; Author: Not shown in title block; CompanyName: Not shown in title block; Engineer: Not shown in title block; Organization: Not shown in title block; Address1: Not shown in title block; Address2: Not shown in title block; Address3: Not shown in title block; Address4: Not shown in title block; DocumentNumber: 1; Revision: Use project parameter SCH_Rev; SheetNumber: 2; SheetTotal: 3; PageSetup: Record=PageOptions¦CenterHorizontal=True¦CenterVertical=True¦PrintScale=1.00¦XCorrection=1.00¦YCorrection=1.00¦PrintKind=0¦BorderSize=5000000¦LeftOffset=0¦BottomOffset=0¦Orientation=2¦PaperLength=1000¦PaperWidth=1000¦Scale=100¦PaperSource=15¦PrintQuality=600¦MediaType=1¦DitherType=10¦PaperKind=Letter¦PrintScaleMode=1
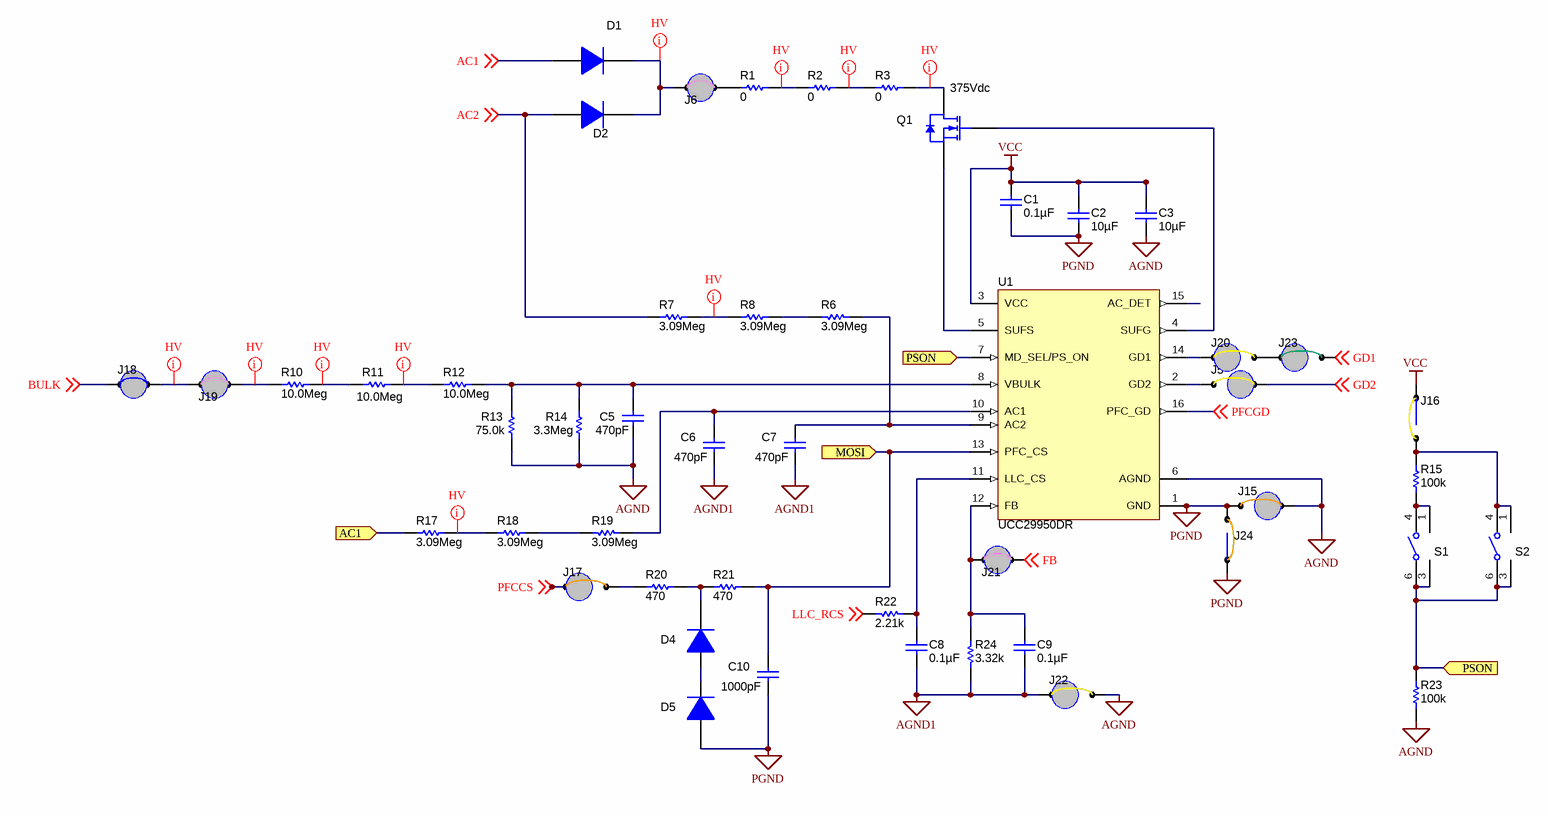
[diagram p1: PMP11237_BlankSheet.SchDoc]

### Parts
C1  ValueDisplayed: 0.1µF  [0603]  (hidden comment: 06035C104KAT2A)
C2  ValueDisplayed: 10µF  [1206]  (hidden comment: GMK316AB7106KL)
C3  ValueDisplayed: 10µF  [1206]  (hidden comment: GMK316AB7106KL)
C5  ValueDisplayed: 470pF  [0603]  (hidden comment: C0603C471K5RACTU)
C6  ValueDisplayed: 470pF  [0603]  (hidden comment: C0603C471K5RACTU)
C7  ValueDisplayed: 470pF  [0603]  (hidden comment: C0603C471K5RACTU)
C8  ValueDisplayed: 0.1µF  [0603]  (hidden comment: 06035C104KAT2A)
C9  ValueDisplayed: 0.1µF  [0603]  (hidden comment: 06033C104KAT2A)
C10  ValueDisplayed: 1000pF  [0603]  (hidden comment: C0603C102K5RACTU)
D1  DA2JF8100L  [SMini2-F5-B]  (value not drawn)
D2  DA2JF8100L  [SMini2-F5-B]  (value not drawn)
D4  BAS316,115  [sod-323]  (value not drawn)
D5  BAS316,115  [sod-323]  (value not drawn)
J5  923345-04-C  [3M_923345-04-C]  (value not drawn)
J6  923345-07-C  [CONN_923345-07-C]  (value not drawn)
J15  923345-03-C  [923345-03-C]  (value not drawn)
J16  923345-04-C  [3M_923345-04-C]  (value not drawn)
J17  923345-03-C  [923345-03-C]  (value not drawn)
J18  923345-06-C  [CONN_923345-06-C]  (value not drawn)
J19  923345-07-C  [CONN_923345-07-C]  (value not drawn)
J20  923345-04-C  [3M_923345-04-C]  (value not drawn)
J21  923345-07-C  [CONN_923345-07-C]  (value not drawn)
J22  923345-04-C  [3M_923345-04-C]  (value not drawn)
J23  923345-05-C  [923345-05-C]  (value not drawn)
J24  923345-03-C  [923345-03-C]  (value not drawn)
Q1  BSS126 H6906  [SOT-23]  (value not drawn)
R1  value 0  [1206]  (hidden comment: CRCW12060000Z0EA)
R2  value 0  [1206]  (hidden comment: CRCW12060000Z0EA)
R3  value 0  [1206]  (hidden comment: CRCW12060000Z0EA)
R6  ValueDisplayed: 3.09Meg  [CMF50_Vertical]  (hidden comment: CMF503M0900FLEK)
R7  value 3.09Meg  [1206]  (hidden comment: CRCW12063M09FKEA)
R8  value 3.09Meg  [1206]  (hidden comment: CRCW12063M09FKEA)
R10  value 10.0Meg  [1206]  (hidden comment: CRCW120610M0FKEA)
R11  value 10.0Meg  [1206]  (hidden comment: CRCW120610M0FKEA)
R12  value 10.0Meg  [1206]  (hidden comment: CRCW120610M0FKEA)
R13  value 75.0k  [0603]  (hidden comment: CRCW060375K0FKEA)
R14  value 3.3Meg  [0603]  (hidden comment: CRCW06033M30JNEA)
R15  ValueDisplayed: 100k  [0603]  (hidden comment: CRCW0603100KFKEA)
R17  value 3.09Meg  [1206]  (hidden comment: CRCW12063M09FKEA)
R18  value 3.09Meg  [1206]  (hidden comment: CRCW12063M09FKEA)
R19  ValueDisplayed: 3.09Meg  [CMF50_Vertical]  (hidden comment: CMF503M0900FLEK)
R20  value 470  [0603]  (hidden comment: RC0603FR-07470RL)
R21  value 470  [0603]  (hidden comment: RC0603FR-07470RL)
R22  ValueDisplayed: 2.21k  [CMF50_Vertical]  (hidden comment: CMF502K2100FHEB)
R23  ValueDisplayed: 100k  [0603]  (hidden comment: CRCW0603100KFKEA)
R24  value 3.32k  [0603]  (hidden comment: CRCW06033K32FKEA)
S1  200USP9T1A1M2RE  [200USP9xxxxM2]  (value not drawn)
S2  200USP9T1A1M2RE  [200USP9xxxxM2]  (value not drawn)
U1  UCC29950DR  [D0016A_N]

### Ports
AC1, MOSI, PSON

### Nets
AGND: C3.1 C5.2 J15.2 J22.1 R13.2 R14.1 R23.1 U1.6(AGND)
AGND1: C6.2 C7.2 C8.2 C9.2 J22.2 R24.2
PGND: C1.2 C2.1 C10.1 D5.2(A) J15.1 J24.1 J24.2 U1.1(GND)
VCC: C1.1 C2.2 C3.2 J16.2 U1.3(VCC)
AC1: D1.2(A) ; off-sheet AC1
AC1: R17.2 ; port AC1  [a separate net that carries the same name]
AC2: D2.2(A) R7.2 ; off-sheet AC2
BULK: J18.2 ; off-sheet BULK
FB: J21.1 ; off-sheet FB
GD1: J23.1 ; off-sheet GD1
GD2: J5.2 ; off-sheet GD2
LLC_RCS: R22.2 ; off-sheet LLC_RCS
MOSI: C10.2 R21.2 U1.13(PFC_CS) ; port MOSI
PFCCS: J17.2 ; off-sheet PFCCS
PFCGD: U1.16(PFC_GD) ; off-sheet PFCGD
PSON: R23.2 S1.3 S1.6 S2.3 S2.6 U1.7(MD_SEL/PS_ON) ; port PSON
NetC5_1: C5.1 R12.2 R13.1 R14.2 U1.8(VBULK)
NetC6_1: C6.1 R19.1 U1.10(AC1)
NetC7_1: C7.1 R6.1 U1.9(AC2)
NetC8_1: C8.1 R22.1 U1.11(LLC_CS)
NetC9_1: C9.1 J21.2 R24.1 U1.12(FB)
NetD1_1: D1.1(K) D2.1(K) J6.2
NetD4_1: D4.1(K) R20.2 R21.1
NetD4_2: D4.2(A) D5.1(K)
NetJ5_1: J5.1 U1.2(GD2)
NetJ6_1: J6.1 R1.1
NetJ16_1: J16.1 R15.2 S2.1 S2.4
NetJ17_1: J17.1 R20.1
NetJ18_1: J18.1 J19.2
NetJ19_1: J19.1 R10.1
NetJ20_1: J20.1 J23.2
NetJ20_2: J20.2 U1.14(GD1)
NetQ1_1: Q1.1(G) U1.4(SUFG)
NetQ1_2: Q1.2(S) U1.5(SUFS)
NetQ1_3: Q1.3(D) R3.2
NetR1_2: R1.2 R2.1
NetR2_2: R2.2 R3.1
NetR6_2: R6.2 R8.1
NetR7_1: R7.1 R8.2
NetR10_2: R10.2 R11.1
NetR11_2: R11.2 R12.1
NetR15_1: R15.1 S1.1 S1.4
NetR17_1: R17.1 R18.2
NetR18_1: R18.1 R19.2

Not connected (* = marked no-connect by the designer): U1 15(AC_DET)

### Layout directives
net class HV: NetD1_1, NetJ18_1, NetJ19_1, NetQ1_3, NetR1_2, NetR2_2, NetR7_1, NetR10_2, NetR11_2, NetR17_1

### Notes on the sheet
- (near Q1) 375Vdc

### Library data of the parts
C1 C8 = 06035C104KAT2A: CAP, CERM, 0.1uF, 50V, +/-10%, X7R, 0603; Manufacturer: AVX; Polarized: N; CompType: Capacitor; U/M: EA; Cap_F: 0.0000001; Tolerance_%: 10; Value1: Unknown; VDC_V: 50; TaMin_C: -55; TaMax_C: 125
C2 C3 = GMK316AB7106KL: CAP, CERM, 10uF, 35V, +/-10%, X7R, 1206; Manufacturer: Taiyo Yuden; Polarized: N; CompType: Capacitor; U/M: EA; Cap_F: 0.00001; Tolerance_%: 10; Value1: Unknown; VDC_V: 35; TaMin_C: -55; TaMax_C: 125
C5-C7 = C0603C471K5RACTU: CAP, CERM, 470pF, 50V, +/-10%, X7R, 0603; Manufacturer: Kemet; Polarized: N; CompType: Capacitor; U/M: EA; Cap_F: 0.00000000047; Tolerance_%: 10; Value1: Unknown; VDC_V: 50; TaMin_C: -55; TaMax_C: 125
C9 = 06033C104KAT2A: CAP, CERM, 0.1uF, 25V, +/-10%, X7R, 0603; Manufacturer: AVX; Polarized: N; CompType: Capacitor; U/M: EA; Cap_F: 0.0000001; Tolerance_%: 10; ESR_Ohm: 0.05; Value1: 0.05 ohm; VDC_V: 25; TaMin_C: -55; TaMax_C: 125
C10 = C0603C102K5RACTU: CAP, CERM, 1000pF, 50V, +/-10%, X7R, 0603; Manufacturer: Kemet; Polarized: N; CompType: Capacitor; U/M: EA; Cap_F: 0.000000001; Tolerance_%: 10; Value1: Unknown; VDC_V: 50; TaMin_C: -55; TaMax_C: 125
D1 D2 = DA2JF8100L: Diode, Fast Rectifier, 800V, 0.2A, TVS, 1.7x.7x1.25mm; Manufacturer: Panasonic; U/M: EA; Vf_V: 2.5; Value2: 2.5V; Io_A: 0.2; Vr_V: 800; TJmax_C: 150
D4 D5 = BAS316,115: as D9 on sheet PMP11237_CoverSheet
J5 J16 J20 J22 = 923345-04-C: Jumper Wire, 400 mil Spacing, Yellow, Pkg of 200; Manufacturer: 3M; SymbolCreator: Altium; U/M: EA
J6 J19 J21 = 923345-07-C: as J1 on sheet PMP11237_CoverSheet
J15 J17 J24 = 923345-03-C: as J9 on sheet PMP11237_CoverSheet
J18 = 923345-06-C: Jumper Wire, 600mil spacing, Blue, pkg of 150, TH; Manufacturer: 3M; SymbolCreator: a0412235; U/M: EA
J23 = 923345-05-C: as J11 on sheet PMP11237_CoverSheet
Q1 = BSS126 H6906: MOSFET, N-CH, 600V, 0.021A, SOT-23; Manufacturer: Infineon Technologies; Alternate Manufacturer: None; U/M: EA; ChType: N; VdsMax_V: 600; Value1: ? ohm; Value2: 1.4 nC; QgTyp_nC: 1.4; Vgs_V: 20; IdsMax_A: 0.021
R1-R3 = CRCW12060000Z0EA: RES, 0 ohm, 5%, 0.25W, 1206; Manufacturer: Vishay-Dale; CompType: Resistor; Value_Code: 0000; Tolerance_%: 5; Power_W: 0.25; VDC_V: 200; TempCo: 200 ppm/C; EIA_Code: E24; U/M: EA
R6 R19 = CMF503K0900FHEB: RES 3.09M OHM 1/4W 1% AXIAL; Manufacturer: Vishay-Dale; CompType: Resistor; Value: 3.09Meg; Res_ohm: 3090; Tolerance_%: 1; Power_W: 0.25; Value2: 0.25W; VDC_V: 200; TempCo: 50 ppm/C; EIA_Code: E96; U/M: EA
R7 R8 R17 R18 = CRCW12063M09FKEA: RES, 3.09Meg ohm, 1%, 0.25W, 1206; Manufacturer: Vishay-Dale; CompType: Resistor; Res_ohm: 3090000; Value_Code: 3M09; Tolerance_%: 1; Power_W: 0.25; VDC_V: 200; TempCo: 100 ppm/C; EIA_Code: E96; U/M: EA
R10-R12 = CRCW120610M0FKEA: RES, 10.0Meg ohm, 1%, 0.25W, 1206; Manufacturer: Vishay-Dale; CompType: Resistor; Res_ohm: 10000000; Value_Code: 10M0; Tolerance_%: 1; Power_W: 0.25; VDC_V: 200; TempCo: 100 ppm/C; EIA_Code: E96; U/M: EA
R13 = CRCW060375K0FKEA: RES, 75.0k ohm, 1%, 0.1W, 0603; Manufacturer: Vishay-Dale; CompType: Resistor; Res_ohm: 75000; Value_Code: 75k0; Tolerance_%: 1; Power_W: 0.1; VDC_V: 75; TempCo: 100 ppm/C; EIA_Code: E96; U/M: EA
R14 = CRCW06033M30JNEA: RES, 3.3Meg ohm, 5%, 0.1W, 0603; Manufacturer: Vishay-Dale; CompType: Resistor; Res_ohm: 3300000; Value_Code: 3M30; Tolerance_%: 5; Power_W: 0.1; VDC_V: 75; TempCo: 200 ppm/C; EIA_Code: E24; U/M: EA
R15 R23 = CRCW0603100KFKEA: as R54 on sheet PMP11237_CoverSheet
R20 R21 = RC0603FR-07470RL: RES, 470 ohm, 1%, 0.1W, 0603; Manufacturer: Yageo America; CompType: Resistor; Value_Code: 470R; Tolerance_%: 1; Power_W: 0.1; VDC_V: 150; TempCo: 200 ppm/C; U/M: EA
R22 = CMF502K2100FHEB: RES, 2.21 k, 1%, 0.25 W, TH; Manufacturer: Vishay-Dale; CompType: Resistor; Value: 2.21k; Res_ohm: 2210; Value_Code: 2k21; Tolerance_%: 1; Power_W: 0.25; Value2: 0.25W; VDC_V: 200; TempCo: 50 ppm/C; EIA_Code: E96; U/M: EA
R24 = CRCW06033K32FKEA: RES, 3.32k ohm, 1%, 0.1W, 0603; Manufacturer: Vishay-Dale; CompType: Resistor; Res_ohm: 3320; Value_Code: 3k32; Tolerance_%: 1; Power_W: 0.1; VDC_V: 75; TempCo: 100 ppm/C; EIA_Code: E96; U/M: EA
S1 S2 = 200USP9T1A1M2RE: Switch, Toggle, SPST, 1Pos, TH; Manufacturer: E-Switch; SymbolCreator: a0411947; VDC_V: 20; SwitchFunction: Off-On; PositionCount: 1; CurrentRating_mA: 400
U1 = UCC29950DR: CCM PFC and LLC Combo Controller, D0016A; Manufacturer: Texas Instruments; SymbolCreator: x0208326; CompType: IC; U/M: EA

## Sheet PMP11237_TID_Hardware.SchDoc
size 431 x 279 mm; Date: Not shown in title block; ApprovedBy: Not shown in title block; CheckedBy: Not shown in title block; Author: Not shown in title block; CompanyName: Not shown in title block; Engineer: Not shown in title block; Organization: Not shown in title block; Address1: Not shown in title block; Address2: Not shown in title block; Address3: Not shown in title block; Address4: Not shown in title block; DocumentNumber: 1; Revision: Use project parameter SCH_Rev; SheetNumber: 3; SheetTotal: 3; PageSetup: Record=PageOptions¦CenterHorizontal=True¦CenterVertical=True¦PrintScale=1.00¦XCorrection=1.00¦YCorrection=1.00¦PrintKind=0¦BorderSize=5000000¦LeftOffset=0¦BottomOffset=0¦Orientation=2¦PaperLength=1000¦PaperWidth=1000¦Scale=100¦PaperSource=15¦PrintQuality=600¦MediaType=1¦DitherType=10¦PaperKind=Letter¦PrintScaleMode=1
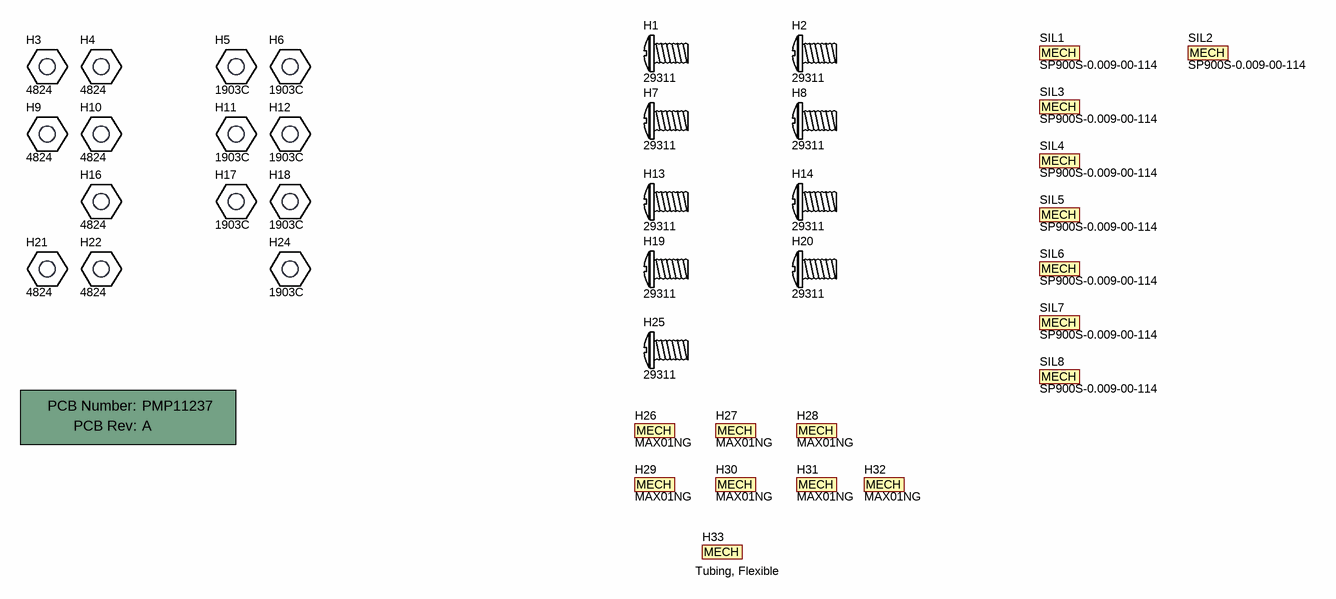
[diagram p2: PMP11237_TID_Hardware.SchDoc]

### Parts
!PCB1  Printed Circuit Board  (value not drawn)  (mechanical)
H1  29311  [Keystone29311]  (mechanical)
H2  29311  [Keystone29311]  (mechanical)
H3  4824  [KEYSTONE_4824]
H4  4824  [KEYSTONE_4824]
H5  1903C  [KEYSTONE_1903C]
H6  1903C  [KEYSTONE_1903C]
H7  29311  [Keystone29311]  (mechanical)
H8  29311  [Keystone29311]  (mechanical)
H9  4824  [KEYSTONE_4824]
H10  4824  [KEYSTONE_4824]
H11  1903C  [KEYSTONE_1903C]
H12  1903C  [KEYSTONE_1903C]
H13  29311  [Keystone29311]  (mechanical)
H14  29311  [Keystone29311]  (mechanical)
H16  4824  [KEYSTONE_4824]
H17  1903C  [KEYSTONE_1903C]
H18  1903C  [KEYSTONE_1903C]
H19  29311  [Keystone29311]  (mechanical)
H20  29311  [Keystone29311]  (mechanical)
H21  4824  [KEYSTONE_4824]
H22  4824  [KEYSTONE_4824]
H24  1903C  [KEYSTONE_1903C]
H25  29311  [Keystone29311]  (mechanical)
H26  MAX01NG  (mechanical)
H27  MAX01NG  (mechanical)
H28  MAX01NG  (mechanical)
H29  MAX01NG  (mechanical)
H30  MAX01NG  (mechanical)
H31  MAX01NG  (mechanical)
H32  MAX01NG  (mechanical)
H33  Type: Tubing, Flexible  (hidden comment: Q2-F-3/64-01-MS100FT)  (mechanical)
SIL1  SP900S-0.009-00-114  (mechanical)
SIL2  SP900S-0.009-00-114  (mechanical)
SIL3  SP900S-0.009-00-114  (mechanical)
SIL4  SP900S-0.009-00-114  (mechanical)
SIL5  SP900S-0.009-00-114  (mechanical)
SIL6  SP900S-0.009-00-114  (mechanical)
SIL7  SP900S-0.009-00-114  (mechanical)
SIL8  SP900S-0.009-00-114  (mechanical)

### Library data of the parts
!PCB1 = PCB: Manufacturer: Any; PartNumber: PMP11237; SymbolCreator: a0412235
H1 H2 H7 H8 H13 H14 H19 H20 H25 = 29311: Screw Pan Head M3; Manufacturer: Keystone; SymbolCreator: a0412235; CompType: Hardware
H3 H4 H9 H10 H16 H21 H22 = 4824: HEX STANDOFF 6-32 NYLON 1-1/2"; Manufacturer: Keystone; SymbolCreator: a0412235
H5 H6 H11 H12 H17 H18 H24 = 1903C: Standoff, Hex, 0.5"L #6-32 Nylon; Manufacturer: Keystone; SymbolCreator: a0412235
H26 = MechPart: MAX Clip; Manufacturer: Aavid Thermalloy; SymbolCreator: codlsc; CompType: Mechanical; U/M: EA
H27-H32 = MechPart: Max Clip; Manufacturer: Aavid Thermalloy; SymbolCreator: codlsc; CompType: Mechanical; U/M: EA
H33 = MechPart: Heatshrink tubing, Digikey pn Q2F364B-100-ND. This is a 100foot reel. we need a qty of about 0.001 per board (aka 50mm) – this will go on the leads of the new diode.; Manufacturer: Qualtek; Shrink Temperature: 70°C; Inner Diameter - Recovered: 0.023" (0.6mm); Inner Diameter - Supplied: 0.046" (1.2mm); Shrinkage Ratio: 2 to 1; Recovered Wall Thickness: 0.016" (0.41mm)
SIL1-SIL8 = MechPart: Silcon Thermal Pad; Manufacturer: Bergquist Company; SymbolCreator: codlsc; U/M: EA; Usage: TO-218, TO-220, TO-247; Shape: Rectangular; Outline: 24.00mm x 21.01mm; Backing, Carrier: Fiberglass; Thermal Resistivity: 0.61°C/W; Thermal Conductivity: 1.6 W/m-K

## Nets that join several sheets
PGND: PMP11237_CoverSheet (19 pins), PMP11237_BlankSheet (8 pins)
VCC: PMP11237_CoverSheet (R4.1 R5.2 R16.1), PMP11237_BlankSheet (5 pins)
AC1: PMP11237_CoverSheet (5 pins), PMP11237_BlankSheet (D1.2)
AC2: PMP11237_CoverSheet (C11.2 F1.1 L2.6 V1.1), PMP11237_BlankSheet (D2.2 R7.2)
BULK: PMP11237_CoverSheet (C14.1 D6.1 J1.2 J3.2), PMP11237_BlankSheet (J18.2)
FB: PMP11237_CoverSheet (R59.2 U5.3 U6.3), PMP11237_BlankSheet (J21.1)
GD1: PMP11237_CoverSheet (J10.1), PMP11237_BlankSheet (J23.1)
GD2: PMP11237_CoverSheet (J9.1), PMP11237_BlankSheet (J5.2)
LLC_RCS: PMP11237_CoverSheet (6 pins), PMP11237_BlankSheet (R22.2)
PFCCS: PMP11237_CoverSheet (6 pins), PMP11237_BlankSheet (J17.2)
PFCGD: PMP11237_CoverSheet (R25.2), PMP11237_BlankSheet (U1.16)

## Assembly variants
001: not fitted C39 C41 C47 D17 R40 R45 R51 R52 R57 R59 U6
